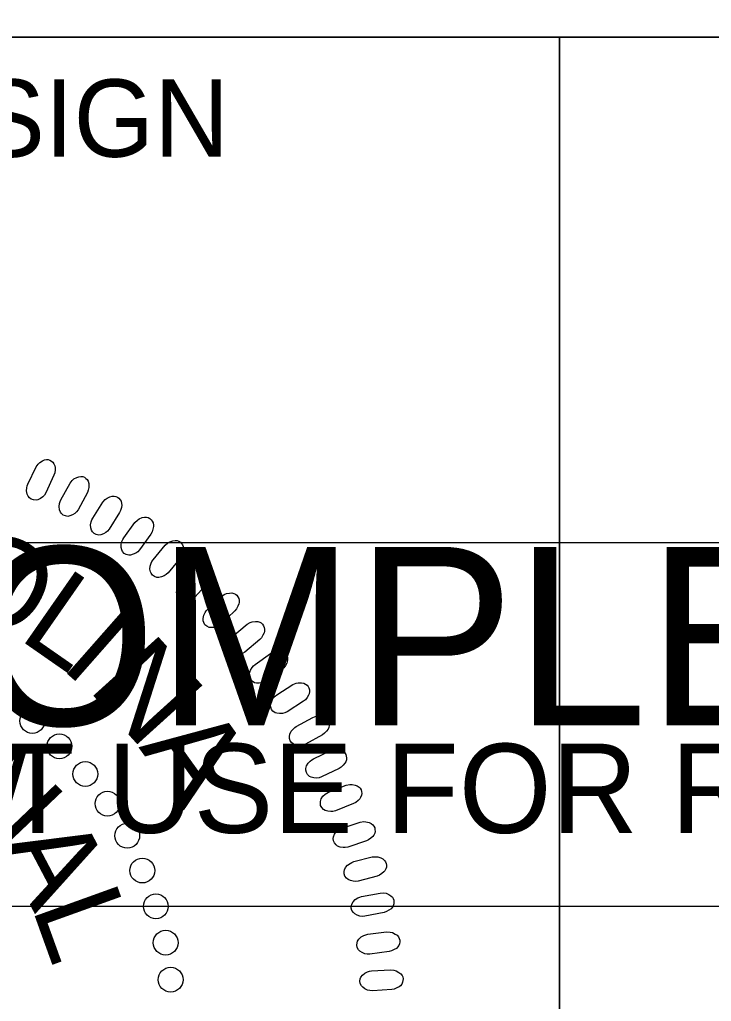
# Model space of a CAD drawing. Extents: x 505569 to 516904, y 436011 to 484484.
# Drawn here: x 507134.2 to 507178.9, y 484096.4 to 484159.8 of the extents above; entities that cross this region are included whole.
import ezdxf

# ---------------------------------------------------------------- set-up
doc = ezdxf.new("R2010")
doc.units = 0
for name, color, linetype in [('Prop Vertical Profile Curve Label', 7, 'Continuous'), ('Prop VPI Label', 7, 'Continuous'), ('Scratch_Level_5', 7, 'Continuous')]:
    doc.layers.add(name, color=color, linetype=linetype)

msp = doc.modelspace()

# ---------------------------------------------------------------- linework, layer by layer
at = {"layer": 'Prop Vertical Profile Curve Label'}
msp.add_line((507169.08, 484158.662), (507169.08, 484046.212), dxfattribs=at)
for points in [[(507069.03, 484183.712), (507269.08, 484183.712), (507269.08, 484158.662), (507069.03, 484158.662)], [(507069.03, 484158.662), (507169.08, 484158.662), (507169.08, 484046.162), (507069.03, 484046.162)], [(507169.08, 484158.662), (507269.08, 484158.662), (507269.08, 484046.162), (507169.08, 484046.162)]]:
    msp.add_lwpolyline(points, close=True, dxfattribs=at)
at = {"layer": 'Prop VPI Label'}
msp.add_lwpolyline([(507095.597, 484102.505), (507095.597, 484126.005), (507242.597, 484126.005), (507242.597, 484102.505)], close=True, dxfattribs=at)
at = {"layer": 'Scratch_Level_5'}
for points in [[(507134.756, 484129.789), (507135.278, 484130.898), (507135.405, 484131.081), (507135.512, 484131.185), (507135.686, 484131.291), (507135.821, 484131.349), (507135.956, 484131.373), (507136.068, 484131.364), (507136.178, 484131.335), (507136.27, 484131.269), (507136.366, 484131.191), (507136.435, 484131.092), (507136.487, 484130.957), (507136.508, 484130.86), (507136.505, 484130.695), (507136.482, 484130.508), (507136.435, 484130.354), (507135.906, 484129.214), (507135.814, 484129.07), (507135.713, 484128.963), (507135.564, 484128.856), (507135.403, 484128.778), (507135.281, 484128.747), (507135.114, 484128.76), (507134.97, 484128.806), (507134.852, 484128.905), (507134.779, 484128.995), (507134.706, 484129.139), (507134.67, 484129.344), (507134.686, 484129.535), (507134.714, 484129.664)], [(507136.88, 484128.774), (507137.471, 484129.848), (507137.609, 484130.022), (507137.722, 484130.119), (507137.902, 484130.214), (507138.04, 484130.263), (507138.177, 484130.279), (507138.288, 484130.264), (507138.396, 484130.227), (507138.485, 484130.155), (507138.575, 484130.071), (507138.638, 484129.969), (507138.682, 484129.831), (507138.695, 484129.732), (507138.683, 484129.569), (507138.648, 484129.383), (507138.591, 484129.232), (507137.992, 484128.127), (507137.89, 484127.99), (507137.784, 484127.889), (507137.629, 484127.792), (507137.462, 484127.724), (507137.339, 484127.701), (507137.173, 484127.724), (507137.032, 484127.779), (507136.92, 484127.886), (507136.852, 484127.98), (507136.789, 484128.129), (507136.766, 484128.335), (507136.794, 484128.524), (507136.83, 484128.653)], [(507138.938, 484127.589), (507139.595, 484128.624), (507139.744, 484128.789), (507139.863, 484128.879), (507140.049, 484128.962), (507140.19, 484129.003), (507140.327, 484129.01), (507140.437, 484128.987), (507140.543, 484128.944), (507140.626, 484128.867), (507140.711, 484128.777), (507140.768, 484128.671), (507140.802, 484128.531), (507140.81, 484128.431), (507140.787, 484128.269), (507140.741, 484128.085), (507140.674, 484127.939), (507140.007, 484126.874), (507139.897, 484126.743), (507139.784, 484126.649), (507139.623, 484126.563), (507139.454, 484126.505), (507139.329, 484126.489), (507139.164, 484126.523), (507139.027, 484126.586), (507138.923, 484126.7), (507138.861, 484126.799), (507138.807, 484126.951), (507138.797, 484127.158), (507138.837, 484127.345), (507138.881, 484127.471)], [(507140.938, 484126.315), (507141.659, 484127.307), (507141.818, 484127.463), (507141.943, 484127.546), (507142.133, 484127.616), (507142.276, 484127.648), (507142.413, 484127.647), (507142.522, 484127.617), (507142.625, 484127.568), (507142.703, 484127.486), (507142.782, 484127.391), (507142.832, 484127.281), (507142.858, 484127.139), (507142.86, 484127.039), (507142.826, 484126.878), (507142.769, 484126.698), (507142.693, 484126.556), (507141.96, 484125.535), (507141.842, 484125.411), (507141.723, 484125.325), (507141.558, 484125.248), (507141.384, 484125.201), (507141.259, 484125.194), (507141.097, 484125.238), (507140.964, 484125.31), (507140.866, 484125.43), (507140.811, 484125.532), (507140.767, 484125.687), (507140.77, 484125.895), (507140.821, 484126.079), (507140.873, 484126.202)], [(507142.832, 484124.899), (507143.614, 484125.844), (507143.783, 484125.989), (507143.912, 484126.063), (507144.107, 484126.123), (507144.251, 484126.145), (507144.389, 484126.135), (507144.495, 484126.099), (507144.594, 484126.042), (507144.668, 484125.957), (507144.741, 484125.856), (507144.783, 484125.744), (507144.8, 484125.6), (507144.796, 484125.501), (507144.751, 484125.343), (507144.683, 484125.166), (507144.599, 484125.029), (507143.804, 484124.056), (507143.678, 484123.94), (507143.554, 484123.861), (507143.384, 484123.795), (507143.208, 484123.759), (507143.082, 484123.759), (507142.923, 484123.813), (507142.795, 484123.894), (507142.705, 484124.02), (507142.657, 484124.125), (507142.623, 484124.283), (507142.639, 484124.489), (507142.701, 484124.671), (507142.761, 484124.79)], [(507144.603, 484123.385), (507145.444, 484124.279), (507145.621, 484124.413), (507145.755, 484124.479), (507145.953, 484124.526), (507146.099, 484124.54), (507146.235, 484124.521), (507146.339, 484124.479), (507146.434, 484124.416), (507146.502, 484124.325), (507146.569, 484124.221), (507146.604, 484124.106), (507146.612, 484123.961), (507146.601, 484123.862), (507146.547, 484123.707), (507146.468, 484123.535), (507146.376, 484123.404), (507145.52, 484122.483), (507145.388, 484122.375), (507145.259, 484122.304), (507145.085, 484122.249), (507144.908, 484122.224), (507144.782, 484122.232), (507144.626, 484122.296), (507144.504, 484122.384), (507144.423, 484122.516), (507144.381, 484122.623), (507144.356, 484122.783), (507144.385, 484122.989), (507144.459, 484123.165), (507144.526, 484123.28)], [(507146.348, 484121.692), (507147.243, 484122.531), (507147.428, 484122.653), (507147.566, 484122.711), (507147.766, 484122.746), (507147.912, 484122.75), (507148.047, 484122.723), (507148.148, 484122.674), (507148.24, 484122.606), (507148.302, 484122.51), (507148.362, 484122.402), (507148.39, 484122.285), (507148.389, 484122.141), (507148.371, 484122.042), (507148.308, 484121.891), (507148.219, 484121.725), (507148.117, 484121.599), (507147.206, 484120.734), (507147.067, 484120.634), (507146.935, 484120.571), (507146.757, 484120.528), (507146.578, 484120.514), (507146.453, 484120.53), (507146.302, 484120.603), (507146.185, 484120.699), (507146.112, 484120.835), (507146.077, 484120.945), (507146.063, 484121.106), (507146.105, 484121.309), (507146.19, 484121.482), (507146.264, 484121.592)], [(507147.96, 484119.945), (507148.905, 484120.727), (507149.099, 484120.838), (507149.24, 484120.887), (507149.441, 484120.908), (507149.588, 484120.903), (507149.721, 484120.868), (507149.818, 484120.812), (507149.906, 484120.739), (507149.961, 484120.639), (507150.014, 484120.528), (507150.035, 484120.409), (507150.025, 484120.265), (507150.001, 484120.168), (507149.929, 484120.021), (507149.829, 484119.861), (507149.72, 484119.742), (507148.756, 484118.935), (507148.611, 484118.845), (507148.475, 484118.79), (507148.295, 484118.758), (507148.116, 484118.755), (507147.992, 484118.779), (507147.846, 484118.862), (507147.736, 484118.965), (507147.671, 484119.105), (507147.643, 484119.217), (507147.639, 484119.379), (507147.693, 484119.579), (507147.789, 484119.746), (507147.87, 484119.851)], [(507149.42, 484118.123), (507150.413, 484118.843), (507150.612, 484118.942), (507150.756, 484118.982), (507150.96, 484118.991), (507151.105, 484118.976), (507151.235, 484118.933), (507151.329, 484118.871), (507151.412, 484118.792), (507151.461, 484118.69), (507151.507, 484118.576), (507151.52, 484118.456), (507151.501, 484118.313), (507151.472, 484118.217), (507151.39, 484118.075), (507151.28, 484117.921), (507151.164, 484117.809), (507150.152, 484117.065), (507150.001, 484116.984), (507149.861, 484116.937), (507149.68, 484116.916), (507149.501, 484116.925), (507149.379, 484116.957), (507149.239, 484117.049), (507149.135, 484117.158), (507149.079, 484117.302), (507149.058, 484117.416), (507149.064, 484117.578), (507149.131, 484117.774), (507149.237, 484117.934), (507149.324, 484118.035)], [(507150.821, 484116.176), (507151.857, 484116.834), (507152.062, 484116.92), (507152.208, 484116.951), (507152.411, 484116.947), (507152.556, 484116.923), (507152.683, 484116.871), (507152.773, 484116.804), (507152.85, 484116.72), (507152.893, 484116.615), (507152.932, 484116.498), (507152.938, 484116.378), (507152.909, 484116.235), (507152.874, 484116.142), (507152.783, 484116.005), (507152.664, 484115.859), (507152.542, 484115.754), (507151.485, 484115.075), (507151.329, 484115.003), (507151.187, 484114.967), (507151.004, 484114.957), (507150.826, 484114.977), (507150.707, 484115.016), (507150.572, 484115.116), (507150.476, 484115.232), (507150.429, 484115.379), (507150.415, 484115.495), (507150.431, 484115.656), (507150.51, 484115.847), (507150.626, 484116), (507150.72, 484116.095)], [(507152.082, 484114.127), (507153.157, 484114.717), (507153.367, 484114.79), (507153.515, 484114.812), (507153.717, 484114.796), (507153.86, 484114.763), (507153.984, 484114.703), (507154.07, 484114.63), (507154.141, 484114.542), (507154.178, 484114.434), (507154.209, 484114.315), (507154.207, 484114.194), (507154.17, 484114.054), (507154.129, 484113.964), (507154.03, 484113.832), (507153.901, 484113.694), (507153.773, 484113.597), (507152.675, 484112.986), (507152.515, 484112.924), (507152.371, 484112.896), (507152.188, 484112.898), (507152.012, 484112.929), (507151.895, 484112.975), (507151.767, 484113.084), (507151.678, 484113.206), (507151.641, 484113.356), (507151.634, 484113.472), (507151.66, 484113.631), (507151.751, 484113.817), (507151.876, 484113.963), (507151.976, 484114.052)], [(507153.189, 484112.044), (507154.299, 484112.566), (507154.514, 484112.625), (507154.662, 484112.638), (507154.864, 484112.608), (507155.004, 484112.567), (507155.124, 484112.499), (507155.205, 484112.422), (507155.271, 484112.328), (507155.3, 484112.218), (507155.324, 484112.097), (507155.315, 484111.978), (507155.269, 484111.84), (507155.222, 484111.752), (507155.115, 484111.627), (507154.978, 484111.497), (507154.843, 484111.409), (507153.709, 484110.868), (507153.546, 484110.816), (507153.4, 484110.797), (507153.219, 484110.81), (507153.044, 484110.853), (507152.93, 484110.906), (507152.809, 484111.023), (507152.728, 484111.15), (507152.7, 484111.302), (507152.701, 484111.418), (507152.737, 484111.576), (507152.84, 484111.756), (507152.974, 484111.893), (507153.079, 484111.975)], [(507154.169, 484109.883), (507155.31, 484110.334), (507155.527, 484110.379), (507155.676, 484110.383), (507155.875, 484110.341), (507156.013, 484110.29), (507156.128, 484110.216), (507156.204, 484110.133), (507156.264, 484110.036), (507156.286, 484109.924), (507156.302, 484109.802), (507156.286, 484109.683), (507156.231, 484109.549), (507156.179, 484109.464), (507156.065, 484109.346), (507155.92, 484109.224), (507155.78, 484109.145), (507154.614, 484108.676), (507154.448, 484108.634), (507154.301, 484108.625), (507154.12, 484108.65), (507153.949, 484108.702), (507153.839, 484108.764), (507153.725, 484108.888), (507153.652, 484109.02), (507153.634, 484109.173), (507153.642, 484109.289), (507153.688, 484109.444), (507153.802, 484109.617), (507153.944, 484109.746), (507154.054, 484109.821)], [(507155.042, 484107.568), (507156.21, 484107.947), (507156.43, 484107.979), (507156.579, 484107.973), (507156.775, 484107.918), (507156.909, 484107.86), (507157.02, 484107.778), (507157.09, 484107.691), (507157.143, 484107.59), (507157.159, 484107.477), (507157.168, 484107.354), (507157.143, 484107.237), (507157.08, 484107.106), (507157.023, 484107.024), (507156.901, 484106.914), (507156.749, 484106.802), (507156.604, 484106.731), (507155.411, 484106.336), (507155.243, 484106.305), (507155.097, 484106.305), (507154.918, 484106.341), (507154.75, 484106.404), (507154.644, 484106.472), (507154.538, 484106.603), (507154.473, 484106.739), (507154.465, 484106.894), (507154.48, 484107.008), (507154.536, 484107.161), (507154.66, 484107.326), (507154.81, 484107.446), (507154.924, 484107.514)], [(507155.788, 484105.396), (507156.976, 484105.7), (507157.197, 484105.718), (507157.346, 484105.703), (507157.538, 484105.636), (507157.669, 484105.569), (507157.773, 484105.48), (507157.838, 484105.389), (507157.885, 484105.285), (507157.894, 484105.171), (507157.894, 484105.048), (507157.863, 484104.933), (507157.792, 484104.806), (507157.73, 484104.728), (507157.601, 484104.626), (507157.442, 484104.523), (507157.293, 484104.462), (507156.078, 484104.143), (507155.908, 484104.122), (507155.762, 484104.131), (507155.585, 484104.178), (507155.422, 484104.252), (507155.32, 484104.326), (507155.224, 484104.463), (507155.167, 484104.604), (507155.169, 484104.758), (507155.191, 484104.872), (507155.256, 484105.02), (507155.39, 484105.178), (507155.548, 484105.287), (507155.666, 484105.349)], [(507156.297, 484103.141), (507157.502, 484103.37), (507157.725, 484103.375), (507157.872, 484103.35), (507158.059, 484103.271), (507158.185, 484103.196), (507158.285, 484103.101), (507158.343, 484103.006), (507158.384, 484102.899), (507158.385, 484102.786), (507158.378, 484102.662), (507158.339, 484102.549), (507158.261, 484102.427), (507158.194, 484102.353), (507158.059, 484102.259), (507157.894, 484102.167), (507157.742, 484102.115), (507156.508, 484101.872), (507156.337, 484101.863), (507156.192, 484101.881), (507156.019, 484101.939), (507155.861, 484102.023), (507155.764, 484102.103), (507155.675, 484102.247), (507155.628, 484102.39), (507155.639, 484102.544), (507155.669, 484102.656), (507155.743, 484102.8), (507155.887, 484102.948), (507156.052, 484103.049), (507156.173, 484103.102)], [(507156.695, 484100.702), (507157.913, 484100.855), (507158.135, 484100.845), (507158.28, 484100.811), (507158.462, 484100.721), (507158.584, 484100.639), (507158.677, 484100.538), (507158.729, 484100.439), (507158.763, 484100.33), (507158.757, 484100.216), (507158.742, 484100.093), (507158.696, 484099.982), (507158.61, 484099.866), (507158.539, 484099.797), (507158.398, 484099.711), (507158.228, 484099.629), (507158.072, 484099.587), (507156.826, 484099.422), (507156.655, 484099.424), (507156.511, 484099.451), (507156.342, 484099.52), (507156.189, 484099.614), (507156.098, 484099.7), (507156.018, 484099.848), (507155.981, 484099.995), (507156.002, 484100.147), (507156.038, 484100.257), (507156.121, 484100.396), (507156.274, 484100.536), (507156.444, 484100.625), (507156.569, 484100.671)], [(507156.939, 484098.337), (507158.163, 484098.413), (507158.384, 484098.39), (507158.527, 484098.347), (507158.704, 484098.245), (507158.819, 484098.155), (507158.905, 484098.048), (507158.951, 484097.946), (507158.979, 484097.836), (507158.966, 484097.723), (507158.944, 484097.601), (507158.89, 484097.493), (507158.797, 484097.382), (507158.721, 484097.318), (507158.576, 484097.241), (507158.401, 484097.17), (507158.243, 484097.138), (507156.989, 484097.052), (507156.819, 484097.064), (507156.676, 484097.1), (507156.512, 484097.18), (507156.366, 484097.283), (507156.28, 484097.374), (507156.21, 484097.528), (507156.181, 484097.676), (507156.211, 484097.827), (507156.255, 484097.935), (507156.346, 484098.068), (507156.508, 484098.198), (507156.683, 484098.277), (507156.81, 484098.314)]]:
    msp.add_lwpolyline(points, close=True, dxfattribs=at)
for centre in [(507135.036, 484114.482), (507136.787, 484112.848), (507138.459, 484111.055), (507139.891, 484109.142), (507141.165, 484107.071), (507142.137, 484104.821), (507143.012, 484102.51), (507143.648, 484100.16), (507143.966, 484097.77)]:
    msp.add_circle(centre, 0.801, dxfattribs=at)

# ---------------------------------------------------------------- texts
at = {"layer": 'Prop Vertical Profile Curve Label'}
msp.add_text('ROADWAY DESIGN', height=5.0001, dxfattribs=at).set_placement((507085.692, 484150.924))
at = {"layer": 'Prop VPI Label'}
for s, height, p in [('INCOMPLETE PLANS', 11.52, (507104.547, 484114.205)), ('DO NOT USE FOR R/W ACQUISITION', 5.76, (507107.797, 484107.255))]:
    msp.add_text(s, height=height, dxfattribs=at).set_placement(p)
at = {"layer": 'Scratch_Level_5'}
for s, rotation, p in [('O', 331.63025, (507129.326, 484122.379)), ('L', 325.14089, (507134.059, 484119.848)), ('I', 318.65154, (507136.752, 484117.995)), ('N', 312.16218, (507138.557, 484116.575)), ('A', 305.67282, (507141.877, 484112.795)), ('N', 313.65025, (507129.525, 484109.537)), ('A', 297.77065, (507132.862, 484106.456)), ('L', 289.83086, (507134.985, 484102.461))]:
    msp.add_text(s, height=5.669, rotation=rotation, dxfattribs=at).set_placement(p)

doc.saveas('drawing.dxf')
